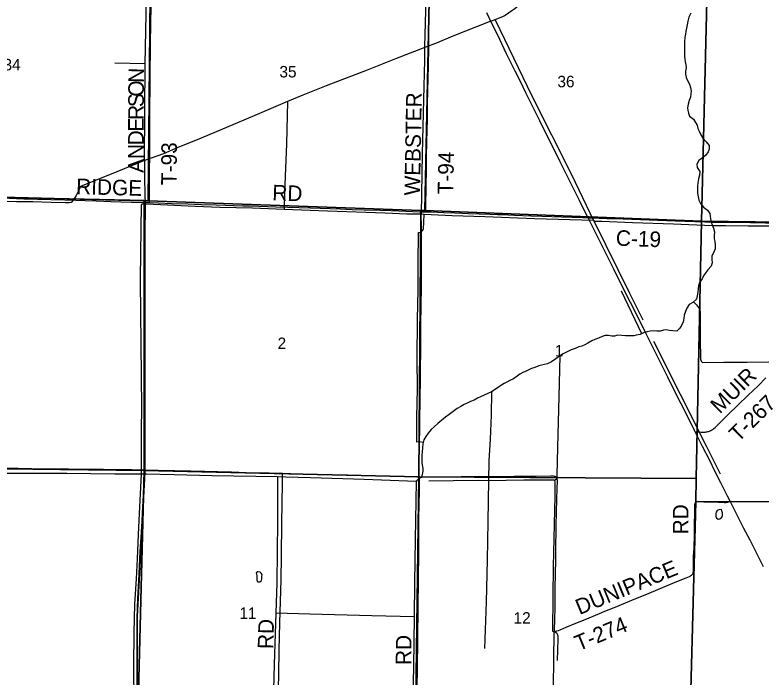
# Model space of a CAD drawing. Extents: x 1443599 to 1910620, y 1028088 to 1361369.
# Drawn here: x 1671995 to 1686339, y 1241579 to 1254320 of the extents above; entities that cross this region are included whole.
import ezdxf

# ---------------------------------------------------------------- set-up
doc = ezdxf.new("R2010")
doc.units = 0
for name, color, linetype in [('GM_X_County_Road', 7, 'Continuous'), ('GM_X_County_Road_Text', 7, 'Continuous'), ('GM_X_Major_River', 7, 'Continuous'), ('GM_X_Minor_Lake', 7, 'Continuous'), ('GM_X_Minor_River', 7, 'Continuous'), ('GM_X_Section', 7, 'Continuous'), ('GM_X_Section_Text', 7, 'Continuous'), ('GM_X_State_Route', 7, 'Continuous'), ('GM_X_Township', 7, 'Continuous'), ('GM_X_Township_Road', 7, 'Continuous'), ('GM_X_Township_Road_Text', 7, 'Continuous')]:
    doc.layers.add(name, color=color, linetype=linetype)

msp = doc.modelspace()

# ---------------------------------------------------------------- linework, layer by layer
at = {"layer": 'GM_X_County_Road'}
for points in [[(1669283, 1250873), (1669757, 1250857), (1670003, 1250849), (1670642, 1250829), (1671019, 1250819), (1671887, 1250792), (1672166, 1250782), (1672690, 1250769), (1672953, 1250762), (1673166, 1250753), (1673346, 1250748), (1673559, 1250743), (1673706, 1250737), (1673837, 1250733), (1674034, 1250726), (1674444, 1250712), (1674510, 1250710)], [(1674510, 1250710), (1674582, 1250708)], [(1674582, 1250708), (1674748, 1250702), (1675011, 1250693), (1675323, 1250684), (1675585, 1250675), (1675865, 1250666), (1676374, 1250648), (1676522, 1250644), (1677014, 1250629), (1677244, 1250621), (1677671, 1250606), (1678246, 1250586), (1678476, 1250579), (1678706, 1250571), (1679018, 1250561), (1679231, 1250554), (1679510, 1250543), (1679773, 1250534), (1679805, 1250533)], [(1679805, 1250533), (1679846, 1250532), (1679892, 1250532)], [(1679892, 1250532), (1679938, 1250530), (1679994, 1250529), (1680240, 1250520), (1680454, 1250513), (1680716, 1250502), (1681126, 1250486), (1681269, 1250481), (1681356, 1250477), (1681602, 1250469), (1681913, 1250457), (1682126, 1250448), (1682504, 1250435), (1682914, 1250420), (1683014, 1250416)], [(1683014, 1250416), (1683078, 1250413), (1683373, 1250406), (1683685, 1250397), (1684685, 1250360), (1685259, 1250338), (1685390, 1250334), (1685620, 1250330), (1686129, 1250324), (1686424, 1250320), (1686982, 1250312), (1687261, 1250306), (1687593, 1250302)]]:
    msp.add_lwpolyline(points, dxfattribs=at)
at = {"layer": 'GM_X_Major_River'}
for points in [[(1682139, 1254635), (1682071, 1254626), (1682003, 1254624), (1681941, 1254621), (1681874, 1254604), (1681806, 1254573), (1681737, 1254534), (1681684, 1254499), (1681607, 1254438), (1681548, 1254397), (1681483, 1254353), (1681420, 1254306), (1681368, 1254282), (1681316, 1254263), (1681208, 1254220), (1681111, 1254185)], [(1681111, 1254185), (1680411, 1253912), (1680114, 1253785), (1679878, 1253695), (1679309, 1253477), (1678769, 1253257), (1677976, 1252955), (1677530, 1252777), (1677237, 1252652), (1676967, 1252541), (1676609, 1252383), (1676064, 1252155), (1675498, 1251919), (1675129, 1251771), (1674850, 1251648), (1674487, 1251517), (1673954, 1251300), (1673259, 1251021), (1673218, 1250935), (1673172, 1250844), (1673122, 1250760), (1673075, 1250713), (1673039, 1250704), (1672967, 1250703), (1672691, 1250708), (1672342, 1250721), (1672026, 1250725), (1671803, 1250733)]]:
    msp.add_lwpolyline(points, dxfattribs=at)
at = {"layer": 'GM_X_Minor_Lake'}
for p, q in [((1685468, 1244728), (1685471, 1244670)), ((1676646, 1243532), (1676645, 1243502))]:
    msp.add_line(p, q, dxfattribs=at)
for points in [[(1685471, 1244670), (1685482, 1244638), (1685511, 1244619), (1685545, 1244624), (1685586, 1244657), (1685597, 1244687), (1685595, 1244739), (1685586, 1244781), (1685575, 1244806), (1685530, 1244797), (1685498, 1244782), (1685475, 1244754), (1685468, 1244728)], [(1676645, 1243502), (1676646, 1243476), (1676643, 1243452), (1676652, 1243418), (1676672, 1243411), (1676702, 1243414), (1676737, 1243437), (1676744, 1243473), (1676741, 1243514), (1676745, 1243554), (1676729, 1243576), (1676708, 1243595), (1676668, 1243602), (1676631, 1243583), (1676646, 1243532)]]:
    msp.add_lwpolyline(points, dxfattribs=at)
at = {"layer": 'GM_X_Minor_River'}
for points in [[(1674487, 1251517), (1674501, 1253378), (1674551, 1255936)], [(1679814, 1250486), (1679829, 1251647), (1679858, 1252690), (1679876, 1253447), (1679875, 1253704), (1679898, 1254642), (1679916, 1255356), (1679924, 1255762)], [(1684989, 1254356), (1684948, 1254277), (1684928, 1254201), (1684916, 1254127), (1684904, 1254063), (1684895, 1254003), (1684883, 1253951), (1684871, 1253883), (1684867, 1253809), (1684867, 1253751), (1684868, 1253699), (1684865, 1253589), (1684867, 1253526), (1684873, 1253466), (1684882, 1253415), (1684890, 1253359), (1684897, 1253305), (1684885, 1253235), (1684883, 1253182), (1684901, 1253114), (1684922, 1253057), (1684960, 1252986), (1684982, 1252923), (1684994, 1252854), (1684991, 1252804), (1684981, 1252738), (1684959, 1252672), (1684937, 1252605), (1684925, 1252535), (1684931, 1252481), (1684942, 1252428), (1684964, 1252373), (1685039, 1252313), (1685079, 1252250), (1685108, 1252198), (1685126, 1252136), (1685147, 1252085), (1685183, 1252014), (1685227, 1251942), (1685285, 1251876), (1685341, 1251806), (1685343, 1251736), (1685324, 1251684), (1685278, 1251624), (1685208, 1251565), (1685142, 1251517), (1685102, 1251448), (1685109, 1251383), (1685161, 1251310), (1685158, 1251236)], [(1681227, 1254227), (1681933, 1252765), (1682694, 1251248), (1683117, 1250363), (1683129, 1250346), (1683809, 1248966), (1684065, 1248454)], [(1674501, 1253378), (1673916, 1253391)], [(1677237, 1252652), (1677217, 1251841), (1677180, 1250900), (1677173, 1250579)], [(1674487, 1251517), (1674488, 1251182), (1674490, 1250873), (1674500, 1250680)], [(1685158, 1251236), (1685136, 1251166), (1685124, 1251090), (1685116, 1251024), (1685116, 1250958), (1685119, 1250893), (1685131, 1250823), (1685143, 1250756), (1685173, 1250691), (1685233, 1250623), (1685306, 1250565), (1685352, 1250497), (1685362, 1250447), (1685369, 1250394), (1685381, 1250334), (1685400, 1250281), (1685424, 1250216), (1685442, 1250145), (1685434, 1250079), (1685434, 1250013), (1685449, 1249963), (1685459, 1249890), (1685455, 1249818), (1685429, 1249752), (1685391, 1249687), (1685391, 1249617), (1685397, 1249550), (1685381, 1249483), (1685317, 1249414), (1685277, 1249363), (1685234, 1249300), (1685204, 1249243), (1685156, 1249170), (1685138, 1249108), (1685132, 1249052), (1685124, 1248988), (1685112, 1248918), (1685095, 1248851), (1685027, 1248788), (1684959, 1248748), (1684913, 1248679), (1684885, 1248616), (1684861, 1248544), (1684853, 1248480), (1684840, 1248414), (1684812, 1248347), (1684778, 1248293), (1684718, 1248235), (1684642, 1248239), (1684572, 1248251), (1684515, 1248263), (1684464, 1248256), (1684396, 1248238), (1684333, 1248238), (1684275, 1248240), (1684207, 1248234), (1684149, 1248221), (1684080, 1248201), (1684015, 1248173), (1683940, 1248155), (1683890, 1248148), (1683840, 1248148), (1683784, 1248145), (1683734, 1248145), (1683660, 1248149), (1683576, 1248155), (1683519, 1248141), (1683469, 1248136), (1683407, 1248152), (1683341, 1248150), (1683282, 1248132), (1683211, 1248102), (1683144, 1248073), (1683083, 1248047), (1683008, 1248001), (1682949, 1247971), (1682894, 1247948), (1682836, 1247934), (1682763, 1247902), (1682688, 1247874), (1682637, 1247853), (1682584, 1247824), (1682533, 1247800), (1682464, 1247756), (1682392, 1247701), (1682308, 1247644), (1682231, 1247606), (1682177, 1247593), (1682118, 1247581), (1682068, 1247568), (1681989, 1247538), (1681926, 1247514), (1681824, 1247465), (1681770, 1247446), (1681702, 1247410), (1681649, 1247371), (1681580, 1247321), (1681510, 1247285), (1681453, 1247255), (1681401, 1247228), (1681350, 1247193)], [(1683117, 1250363), (1681984, 1250395), (1681027, 1250433), (1680400, 1250457), (1679860, 1250482), (1679814, 1250486), (1679527, 1250488), (1679113, 1250504), (1678004, 1250546), (1677507, 1250566), (1677173, 1250579), (1676560, 1250599), (1675937, 1250617), (1675457, 1250637), (1674659, 1250675), (1674500, 1250680), (1674420, 1250673), (1674405, 1249252), (1674407, 1248533), (1674414, 1248067), (1674420, 1247302), (1674427, 1246830), (1674425, 1246262), (1674425, 1245869), (1674422, 1245483)], [(1679841, 1246092), (1679773, 1246104), (1679721, 1246100), (1679721, 1246576), (1679732, 1247123), (1679730, 1247698), (1679736, 1248458), (1679746, 1249028), (1679750, 1249522), (1679752, 1250132), (1679786, 1250139), (1679814, 1250148), (1679847, 1250199), (1679860, 1250482)], [(1687395, 1250242), (1686704, 1250254), (1686090, 1250253), (1685658, 1250262), (1685399, 1250265), (1684657, 1250292), (1683866, 1250319), (1683277, 1250346), (1683129, 1250346)], [(1684046, 1248186), (1683658, 1249004)], [(1685039, 1248800), (1685095, 1248742), (1685138, 1248693), (1685163, 1248652), (1685171, 1248591), (1685165, 1248379), (1685168, 1248051), (1685173, 1247736), (1685176, 1247696), (1685185, 1247655), (1685212, 1247633), (1685625, 1247639), (1686074, 1247640), (1686485, 1247644), (1687029, 1247651), (1687504, 1247651)], [(1684272, 1248043), (1684782, 1247023), (1685288, 1246014), (1685552, 1245487)], [(1682472, 1247761), (1682451, 1246969), (1682424, 1246004), (1682414, 1245458), (1682411, 1245399), (1682398, 1245383), (1682370, 1245363)], [(1681350, 1247193), (1681294, 1247159), (1681227, 1247113), (1681156, 1247068), (1681084, 1247034), (1681013, 1247004), (1680948, 1246974), (1680885, 1246944), (1680824, 1246909), (1680755, 1246879), (1680690, 1246847), (1680633, 1246822), (1680566, 1246784), (1680497, 1246746), (1680446, 1246711), (1680395, 1246673), (1680343, 1246632), (1680272, 1246578), (1680202, 1246522), (1680126, 1246458), (1680054, 1246395), (1679994, 1246341), (1679938, 1246274), (1679894, 1246207), (1679855, 1246142), (1679834, 1246067), (1679832, 1245988), (1679826, 1245916), (1679818, 1245846), (1679816, 1245780), (1679816, 1245714), (1679821, 1245657), (1679839, 1245593), (1679835, 1245543), (1679813, 1245421)], [(1681156, 1247068), (1681149, 1246617), (1681128, 1246158), (1681106, 1245737), (1681101, 1245364), (1681086, 1244571), (1681073, 1243827), (1681051, 1243028), (1681021, 1242132)], [(1679706, 1245343), (1678711, 1245384), (1677675, 1245412), (1677205, 1245425), (1677044, 1245430), (1675784, 1245454), (1675059, 1245469), (1674525, 1245482), (1674422, 1245483), (1673919, 1245486), (1672994, 1245498), (1672332, 1245495), (1671775, 1245499), (1671090, 1245503), (1670521, 1245515), (1669786, 1245532), (1669181, 1245541)], [(1674422, 1245483), (1674385, 1244724), (1674365, 1244323), (1674346, 1243857), (1674323, 1243467), (1674295, 1242980), (1674280, 1242432), (1674274, 1241796), (1674279, 1241081)], [(1677044, 1245430), (1677044, 1244581), (1677031, 1243399), (1677014, 1242807), (1676980, 1241820), (1676950, 1240860), (1676931, 1240230), (1676897, 1238779), (1676888, 1238039), (1676871, 1237228), (1676861, 1236648), (1676855, 1236428), (1677102, 1236617), (1677378, 1236850), (1677605, 1237032), (1677733, 1237141), (1677870, 1237258), (1678049, 1237403)], [(1679813, 1245421), (1679755, 1245394), (1679724, 1245361), (1679706, 1245343), (1679688, 1244226), (1679678, 1243399), (1679673, 1242739), (1679660, 1241773), (1679640, 1240923), (1679620, 1239787), (1679614, 1238876), (1679596, 1238049), (1679569, 1237520), (1679038, 1237533), (1678776, 1237537), (1678504, 1237546)], [(1679952, 1245358), (1680422, 1245361), (1680903, 1245365), (1681101, 1245364), (1681779, 1245376), (1682238, 1245377), (1682322, 1245375), (1682354, 1245372), (1682370, 1245363), (1682377, 1245339), (1682373, 1245062), (1682361, 1244512), (1682345, 1243706), (1682334, 1243128), (1682327, 1242462), (1682379, 1242448), (1682412, 1242425), (1682433, 1242370), (1682431, 1242306), (1682421, 1241895)], [(1679673, 1242739), (1678858, 1242760), (1677667, 1242792), (1677014, 1242807)]]:
    msp.add_lwpolyline(points, dxfattribs=at)
at = {"layer": 'GM_X_Section'}
for points in [[(1669356, 1256115), (1674609, 1256003), (1674557, 1250741), (1674481, 1250744), (1669268, 1250877)], [(1674609, 1256003), (1679986, 1255840), (1679872, 1250557), (1679800, 1250556), (1674557, 1250741)], [(1685320, 1255659), (1685196, 1250354), (1679872, 1250557), (1679986, 1255840)], [(1685320, 1255659), (1690974, 1255593), (1690967, 1252219), (1690934, 1250281), (1690884, 1250279), (1685196, 1250354)], [(1669268, 1250877), (1674481, 1250744), (1674481, 1245556), (1669117, 1245619), (1669128, 1250879)], [(1674557, 1250741), (1679800, 1250556), (1679757, 1245430), (1674481, 1245556), (1674481, 1250744)], [(1679800, 1250556), (1679872, 1250557), (1685196, 1250354), (1685094, 1245401), (1679757, 1245430)], [(1685196, 1250354), (1690884, 1250279), (1690707, 1244955), (1685086, 1244953), (1685094, 1245401)], [(1669117, 1245619), (1674481, 1245556), (1674345, 1240301), (1669071, 1240359)], [(1679757, 1245430), (1679688, 1240186), (1674346, 1240273), (1674345, 1240301), (1674481, 1245556)], [(1679757, 1245430), (1685094, 1245401), (1685086, 1244953), (1684954, 1240120), (1679688, 1240186)], [(1685086, 1244953), (1690707, 1244955), (1690543, 1239680), (1684949, 1239688), (1684954, 1240120)]]:
    msp.add_lwpolyline(points, close=True, dxfattribs=at)
at = {"layer": 'GM_X_State_Route'}
msp.add_lwpolyline([(1686388, 1243701), (1686317, 1243840), (1686257, 1243957), (1686126, 1244213), (1686010, 1244439), (1685888, 1244681), (1685743, 1244966), (1685695, 1245061), (1685625, 1245201), (1685566, 1245318), (1685459, 1245530), (1685345, 1245758), (1685215, 1246014), (1685075, 1246295), (1685061, 1246323), (1684987, 1246469), (1684802, 1246835), (1684625, 1247187), (1684544, 1247349), (1684219, 1248003), (1684128, 1248186), (1683974, 1248495), (1683826, 1248788), (1683651, 1249141), (1683508, 1249427), (1683097, 1250249), (1683014, 1250416), (1683005, 1250433), (1682850, 1250749), (1682478, 1251491), (1682329, 1251792), (1682223, 1252005), (1682084, 1252284), (1681982, 1252490), (1681902, 1252652), (1681826, 1252807), (1681707, 1253050), (1681612, 1253241), (1681448, 1253572), (1681269, 1253941), (1681166, 1254156), (1681068, 1254363)], dxfattribs=at)
at = {"layer": 'GM_X_Township'}
for points in [[(1695686, 1234412), (1693554, 1234401), (1689711, 1234366), (1684807, 1234336), (1684814, 1234779), (1682213, 1234819), (1679582, 1234813), (1676891, 1234863), (1674317, 1234889), (1674286, 1234890), (1674292, 1235244), (1674346, 1240281), (1674346, 1242746), (1674370, 1243215), (1674492, 1245523), (1674492, 1250747), (1671577, 1250816), (1669283, 1250871), (1669367, 1256110)], [(1671577, 1250816), (1674492, 1250747), (1674492, 1245523), (1674370, 1243215), (1674346, 1242746), (1674346, 1240281), (1674292, 1235244), (1674286, 1234890), (1674317, 1234889), (1676891, 1234863), (1679582, 1234813), (1682213, 1234819), (1684814, 1234779), (1684807, 1234336), (1684762, 1232099), (1684757, 1231793), (1684707, 1229066)]]:
    msp.add_lwpolyline(points, dxfattribs=at)
at = {"layer": 'GM_X_Township_Road'}
for points in [[(1674582, 1250708), (1674583, 1250902), (1674584, 1251231), (1674585, 1251378), (1674587, 1251559), (1674588, 1251822), (1674591, 1252462), (1674594, 1253021), (1674595, 1253251), (1674597, 1253365), (1674600, 1253513), (1674604, 1253776), (1674609, 1254137), (1674615, 1254498), (1674633, 1255845), (1674636, 1255992), (1674636, 1256002)], [(1679892, 1250532), (1679893, 1250590), (1679894, 1250688), (1679899, 1250967), (1679907, 1251410), (1679910, 1251590), (1679916, 1251885), (1679924, 1252312), (1679929, 1252607), (1679943, 1253345), (1679950, 1253690), (1679952, 1253903), (1679955, 1254067), (1679964, 1254691), (1679969, 1255052), (1679973, 1255216), (1679975, 1255363), (1679978, 1255593), (1679979, 1255724), (1679979, 1255790), (1679979, 1255817)], [(1674494, 1248776), (1674495, 1248918), (1674498, 1249508), (1674500, 1249919), (1674501, 1250132), (1674506, 1250608), (1674508, 1250673), (1674510, 1250710)], [(1679768, 1245434), (1679765, 1245450), (1679764, 1245458), (1679763, 1245467), (1679763, 1245513), (1679764, 1245535), (1679768, 1245897), (1679778, 1246339), (1679781, 1246634), (1679785, 1246798), (1679787, 1247011), (1679789, 1247241), (1679790, 1247437), (1679796, 1247929), (1679800, 1248355), (1679806, 1248732), (1679810, 1249076), (1679814, 1249781), (1679814, 1250043), (1679813, 1250141), (1679809, 1250305), (1679805, 1250419), (1679805, 1250501), (1679805, 1250533)], [(1674487, 1245568), (1674487, 1245586), (1674488, 1245685), (1674489, 1245865), (1674489, 1246013), (1674491, 1246177), (1674492, 1246423), (1674493, 1246883), (1674491, 1247359), (1674490, 1247638), (1674492, 1248163), (1674494, 1248507), (1674494, 1248776)], [(1685075, 1246295), (1685109, 1246295), (1685140, 1246295), (1685185, 1246293), (1685234, 1246293), (1685267, 1246294), (1685283, 1246296), (1685299, 1246299), (1685315, 1246303), (1685331, 1246307), (1685346, 1246313), (1685362, 1246319), (1685376, 1246326), (1685391, 1246334), (1685405, 1246343), (1685418, 1246352), (1685431, 1246362), (1685456, 1246383), (1685504, 1246428), (1685598, 1246521), (1685715, 1246636), (1685891, 1246808), (1686092, 1247001), (1686280, 1247184), (1686432, 1247334)], [(1671765, 1245600), (1672060, 1245597), (1672323, 1245594), (1672798, 1245589), (1673028, 1245588), (1673504, 1245582), (1673701, 1245579), (1673930, 1245576), (1674242, 1245574), (1674455, 1245569), (1674487, 1245568)], [(1674342, 1240228), (1674343, 1240311), (1674341, 1240559), (1674343, 1240921), (1674343, 1241118), (1674345, 1241364), (1674344, 1241577), (1674348, 1241839), (1674351, 1242131), (1674350, 1242332), (1674351, 1242628), (1674351, 1242792), (1674354, 1242907), (1674361, 1243088), (1674377, 1243432), (1674404, 1243989), (1674426, 1244366), (1674439, 1244579), (1674447, 1244727), (1674466, 1245088), (1674482, 1245465), (1674484, 1245544), (1674487, 1245568)], [(1674487, 1245568), (1674750, 1245562), (1675374, 1245548), (1676161, 1245527), (1676439, 1245518), (1676882, 1245508), (1677141, 1245502)], [(1677059, 1241360), (1677067, 1241639), (1677078, 1242098), (1677090, 1242623), (1677106, 1243246), (1677112, 1243459), (1677118, 1243902), (1677128, 1244557), (1677132, 1244902), (1677138, 1245345), (1677140, 1245476), (1677141, 1245502)], [(1677141, 1245502), (1677292, 1245498), (1677751, 1245485), (1678047, 1245478), (1678391, 1245470), (1679129, 1245449), (1679719, 1245435), (1679768, 1245434)], [(1679730, 1241433), (1679731, 1241695), (1679739, 1242352), (1679745, 1242877), (1679752, 1243500), (1679758, 1243927), (1679758, 1244124), (1679762, 1244385), (1679763, 1244648), (1679766, 1244879), (1679771, 1245177), (1679772, 1245391), (1679771, 1245402), (1679771, 1245413), (1679768, 1245434)], [(1679768, 1245434), (1679851, 1245432), (1679998, 1245433), (1680573, 1245437), (1680753, 1245439), (1681016, 1245440), (1681196, 1245441), (1681590, 1245442), (1682016, 1245447), (1682295, 1245452), (1682328, 1245451), (1682344, 1245450), (1682359, 1245447), (1682375, 1245443), (1682389, 1245437), (1682396, 1245431), (1682401, 1245428)], [(1682365, 1242460), (1682367, 1242490), (1682368, 1242516), (1682374, 1242663), (1682378, 1242941), (1682380, 1243090), (1682382, 1243287), (1682387, 1243566), (1682391, 1243828), (1682394, 1244008), (1682403, 1244485), (1682408, 1244764), (1682413, 1244992), (1682419, 1245220), (1682423, 1245339), (1682423, 1245371), (1682422, 1245392), (1682418, 1245405), (1682411, 1245418), (1682401, 1245428)], [(1682365, 1242460), (1682385, 1242462), (1682397, 1242463), (1682412, 1242467), (1682443, 1242477), (1682474, 1242489), (1682595, 1242539), (1682777, 1242614), (1682959, 1242689), (1683232, 1242802), (1683338, 1242846), (1683535, 1242927), (1683732, 1243008), (1683929, 1243089), (1684141, 1243177), (1684399, 1243283), (1684520, 1243334), (1684717, 1243416), (1684899, 1243490), (1684960, 1243516), (1684974, 1243523), (1684989, 1243531), (1685002, 1243540), (1685013, 1243550), (1685025, 1243565), (1685031, 1243578), (1685035, 1243596), (1685037, 1243612), (1685039, 1243629), (1685039, 1243645), (1685039, 1243694), (1685041, 1243842), (1685043, 1243907), (1685051, 1244055), (1685055, 1244153), (1685057, 1244235), (1685057, 1244317), (1685058, 1244350), (1685061, 1244530), (1685063, 1244727), (1685063, 1244841), (1685064, 1244874), (1685065, 1244891), (1685068, 1244907), (1685071, 1244920), (1685074, 1244927), (1685076, 1244933), (1685080, 1244938), (1685085, 1244943), (1685089, 1244946), (1685095, 1244951), (1685103, 1244955), (1685111, 1244958), (1685118, 1244960), (1685127, 1244960), (1685140, 1244960), (1685159, 1244959), (1685241, 1244954), (1685290, 1244953), (1685421, 1244948), (1685520, 1244944), (1685584, 1244942), (1685635, 1244940), (1685667, 1244940), (1685683, 1244942), (1685695, 1244944), (1685704, 1244947), (1685714, 1244952), (1685743, 1244966)], [(1682320, 1238920), (1682321, 1238957), (1682321, 1239087), (1682321, 1239218), (1682320, 1239399), (1682324, 1239612), (1682331, 1240055), (1682335, 1240301), (1682338, 1240547), (1682347, 1240989), (1682348, 1241154), (1682349, 1241351), (1682351, 1241598), (1682353, 1241710), (1682357, 1242073), (1682359, 1242269), (1682361, 1242369), (1682364, 1242430), (1682365, 1242460)]]:
    msp.add_lwpolyline(points, dxfattribs=at)

# ---------------------------------------------------------------- texts
at = {"layer": 'GM_X_County_Road_Text'}
for s, rotation, p in [('RIDGE', 358.4336, (1673168, 1250872)), ('RD', 358.0304, (1676938, 1250753)), ('C-19', 357.9418, (1683543, 1249881))]:
    msp.add_text(s, height=300, rotation=rotation, dxfattribs=at).set_placement(p)
at = {"layer": 'GM_X_Section_Text'}
for s, p in [('34', (1671776, 1253253)), ('35', (1677080, 1253117)), ('36', (1682424, 1252928)), ('2', (1677045, 1247891)), ('1', (1682375, 1247749)), ('11', (1676310, 1242698)), ('12', (1681581, 1242607))]:
    msp.add_text(s, height=221, rotation=0, dxfattribs=at).set_placement(p)
at = {"layer": 'GM_X_Township_Road_Text'}
for s, rotation, p in [('N', 89.1257, (1674475, 1253011)), ('O', 89.7377, (1674474, 1252747)), ('S', 89.7434, (1674473, 1252545)), ('WEBSTER', 88.9715, (1679782, 1250844)), ('R', 89.7483, (1674472, 1252299)), ('E', 89.7429, (1674471, 1252074)), ('D', 89.7465, (1674470, 1251810)), ('N', 89.7413, (1674468, 1251546)), ('T-93', 89.6512, (1675106, 1251044)), ('T-94', 88.9394, (1680421, 1250864)), ('A', 89.745, (1674467, 1251282)), ('MUIR', 44.4441, (1685546, 1246632)), ('T-267', 44.4061, (1685901, 1246087)), ('RD', 90, (1684943, 1244325)), ('DUNIPACE', 22.4025, (1682848, 1242771)), ('RD', 88.5175, (1676962, 1242115)), ('T-274', 22.4248, (1682831, 1242075)), ('RD', 89.5063, (1679615, 1241810))]:
    msp.add_text(s, height=300, rotation=rotation, dxfattribs=at).set_placement(p)

doc.saveas('drawing.dxf')
